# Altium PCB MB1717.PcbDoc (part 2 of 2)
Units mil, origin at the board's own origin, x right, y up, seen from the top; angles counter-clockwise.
Board outline 2760.94 x 3253.06 mil, 2 copper layers (Top Layer, Bottom Layer), stack 60.756 mil thick; 141 components, 128 nets, 519 pads, 417 vias.
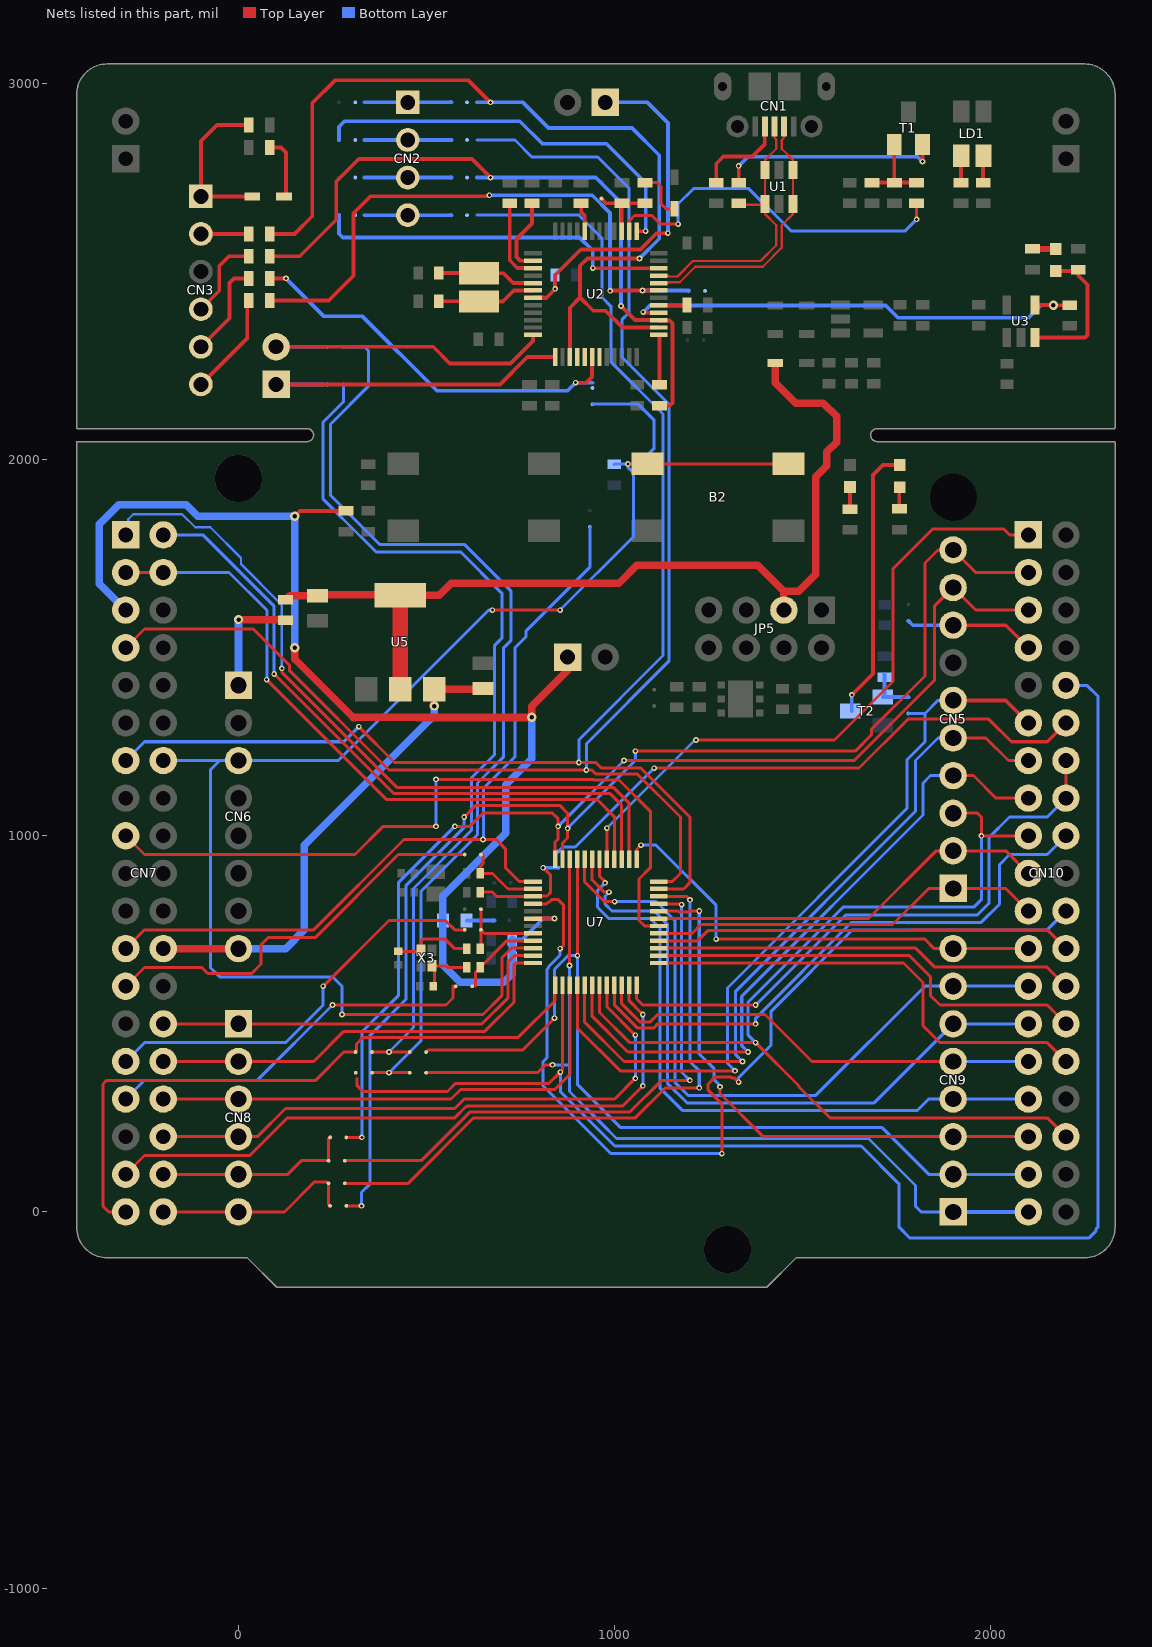
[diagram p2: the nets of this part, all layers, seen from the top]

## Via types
v1: diameter 15, hole 8, Top Layer to Bottom Layer, tented both sides, 383 vias
v2: diameter 25, hole 12, Top Layer to Bottom Layer, tented both sides, 19 vias
v3: diameter 15, hole 8, Top Layer to Bottom Layer, 15 vias

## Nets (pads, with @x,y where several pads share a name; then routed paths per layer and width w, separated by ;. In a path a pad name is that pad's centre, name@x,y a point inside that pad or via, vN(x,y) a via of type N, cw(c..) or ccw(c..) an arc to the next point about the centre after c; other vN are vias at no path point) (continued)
NetC25_2: C25.2 R33.1 X3.1 | length 220.4
  Top Layer w8: C25.2@425,692.72 482.28,692.72 X3.1@485.24,695.67 485.24,720.24 490,725 550,725 575,700 R33.1@607.28,700
NetC26_2: C26.2 R34.1 X3.3 | length 146.2
  Top Layer w8: X3.3@514.76,654.33 550.67,654.33 555,650 R34.1@607.28,650 ; C26.2@517.72,600 520.67,602.95 520.67,648.43 X3.3@522.24,650
NetCN1_4: CN1.4 R13.1 | length 244
  Top Layer w10: R13.1@1270,2740.5 1270,2787 1289,2806 1366,2806 1399.41,2839.41 CN1.4@1399.41,2885.79
NetCN2_1: CN2.1 SB11.2 SB12.1 | length 231.5
  Bottom Layer w10: 334.75,2950 CN2.1@450,2950 SB11.2@566.25,2950
NetCN2_2: CN2.2 SB13.2 SB14.1 | length 231.5
  Bottom Layer w10: 334.75,2850 CN2.2@450,2850 SB13.2@566.25,2850
NetCN2_3: CN2.3 SB15.2 SB16.1 | length 231.5
  Bottom Layer w10: 334.75,2750 CN2.3@450,2750 SB15.2@566.25,2750
NetCN2_4: CN2.4 SB17.2 SB18.1 | length 231.5
  Bottom Layer w10: 334.75,2650 CN2.4@450,2650 SB17.2@566.25,2650
NetCN3_1: CN3.1 D2.1 R1.1 | length 420.1
  Top Layer w10: R1.1@23.5,2890 -57,2890 -100,2847 CN3.1@-100,2700 D2.1@31.76,2700
NetCN3_2: CN3.2 R15.1 | length 123.5
  Top Layer w10: CN3.2@-100,2600 R15.1@23.5,2600
NetCN3_4: CN3.4 R18.1 | length 220.6
  Top Layer w10: CN3.4@-100,2400 -51,2449 -51,2515 -25,2541 R18.1@23.51,2541
NetCN3_5: CN3.5 R19.1 | length 254
  Top Layer w10: CN3.5@-100,2300 -24,2376 -24,2470 -12,2482 R19.1@23.51,2482
NetCN3_6: CN3.6 R20.1 | length 274.2
  Top Layer w10: CN3.6@-100,2200 23.51,2323.51 R20.1@23.51,2423
NetCN5_8: CN5.8 CN10.7 SB25.1 | length 348.6
  Top Layer w10: CN5.8@1900,1560 2040,1560 CN10.7@2100,1500
  Bottom Layer w10: SB25.1@1781,1571.38 1792.38,1560 CN5.8@1900,1560
NetCN6_1: CN6.1 R30.2 | length 301.1
  Top Layer w20: v2(0,1575) 122.44,1575 R30.2@125,1572.44
  Bottom Layer w20: CN6.1@0,1400 v2(0,1575)
NetCN7_25: CN7.25 SB3.2 | length 1089.5
  Top Layer w8: CN7.25@-300,600 -250,650 -97.63,650 -81.63,634 35,634 60,659 60,710 80,730 205,730 425,950 SB3.2@601.38,950
NetCN7_29: CN7.29 SB5.2 | length 1096.4
  Top Layer w8: v1(225,600) 400,775 550,775 575,750 SB5.2@601.38,750
  Bottom Layer w8: CN7.29@-300,400 -250,450 125,450 225,550 v1(225,600)
NetCN7_31: CN7.31 SB6.2 | length 1023.6
  Top Layer w8: v1(250,550) 551.38,550 570,568.62 570,592.24 ; 570,600 570,592.24 ; SB6.2@577.76,600 570,592.24
  Bottom Layer w8: CN7.31@-300,300 -250,350 50,350 v1(250,550)
NetCN7_36: CN7.36 CN8.5 SB7.1 SB8.2 | length 520.3
  Top Layer w8: CN7.36@-200,100 CN8.5@0,100 131,100 167,136 SB8.2@239.38,136 239.38,195.06 SB7.1@244.32,200
NetCN7_38: CN7.38 CN8.6 SB9.2 SB10.1 | length 529.4
  Top Layer w8: CN7.38@-200,0 CN8.6@0,0 122,0 201,79 235,79 ; SB9.2@239.38,76 239.38,19.94 SB10.1@243.32,16
NetCN10_12: CN10.12 SB4.1 | length 1541.2
  Top Layer w8: v3(1105,1180) 1650,1180 1780,1310 1995,1310 2055,1250 2150,1250 CN10.12@2200,1300
  Bottom Layer w8: SB4.1@850,958.31 861.69,970 895,970 v3(1105,1180)
NetD1_2: D1.2 R7.1 | length 133.7
  Top Layer w8: R7.1@1081,2736.56 1113.3,2736.56 1123.57,2726.29 1123.57,2680.46 1137.15,2666.87 D1.2@1159,2666.87
NetD2_2: D2.2 R2.1 | length 162
  Top Layer w10: R2.1@86.5,2830 113,2830 126.24,2816.76 D2.2@126.24,2700
NetL1_1: L1.1 SB30.2 | length 73.8
  Bottom Layer w10: L1.1@607.73,774.61 681.55,774.61
NetLD1_2: LD1.2 R12.2 | length 67.6
  Top Layer w10: LD1.2@1979.53,2807.94 1979.53,2740.97 R12.2@1980,2740.5
NetLD1_3: LD1.3 R11.2 | length 66.9
  Top Layer w10: R11.2@1921,2740.5 LD1.3@1921,2807.42
NetLD2_1: LD2.1 R16.1 | length 62
  Top Layer w16: R16.1@2111,2560.56 LD2.1@2172.97,2560.56
NetLD2_2: LD2.2 R17.1 U3.3 | length 386.2
  Top Layer w10: U3.3@2117.4,2324.69 2250.4,2324.69 2257,2331.29 2257,2465 2232.64,2489.36 R17.1@2232.64,2501.47 ; LD2.2@2173,2501.47 R17.1@2232.64,2501.47 ; R17.1@2232.64,2505.44 R17.1@2232.64,2501.47
NetLD3_1: LD3.1 R28.2 | length 58.6
  Top Layer w10: R28.2@1626,1868.56 LD3.1@1626,1927.17
NetLD4_1: LD4.1 R27.1 | length 58
  Top Layer w10: R27.1@1757,1868.86 1757,1925.47 LD4.1@1758,1926.47
NetLD4_2: LD4.2 T2.3 | length 733.5
  Top Layer w10: v1(1630.69,1374.69) 1687,1431 1687,1959.31 1713.21,1985.53 LD4.2@1758,1985.53
  Bottom Layer w10: T2.3@1630.69,1331 v1(1630.69,1374.69)
NetR3_2: R3.2 U2.3 | length 221.5
  Top Layer w10: R3.2@721,2681.44 721,2530 741.32,2509.68 U2.3@780,2509.68 ; U2.3@780,2508.9 U2.3@782.68,2508.9
NetR4_2: R4.2 U2.2 | length 207.4
  Top Layer w10: R4.2@780,2681.44 780,2628 739,2587 739,2539 749.42,2528.58 U2.2@782.68,2528.58
NetR5_2: R5.2 U2.44 | length 78
  Top Layer w10: R5.2@911,2681.44 911,2658.47 920.47,2649 U2.44@920.47,2607.32
NetR6_1: R6.1 R7.2 SB1.2 U2.39 | length 189.3
  Top Layer w10: SB1.2@965,2694.09 977.65,2681.44 R6.1@1020,2681.44 R7.2@1080,2681.44 ; U2.39@1018.9,2607.32 R6.1@1018.9,2676.4
NetR8_2: R8.2 T1.2 | length 595.8
  Top Layer w10: R8.2@1330,2740.5 v1(1330,2781) ; v1@1817,2791 v1(1818.4,2792.4) T1.2@1818.4,2837.69 ; T1.2@1820.58,2837.69 T1.2@1820.58,2841.63
  Bottom Layer w10: v1(1330,2781) 1354.58,2805.58 1805.22,2805.58 v1(1818.4,2792.4)
NetR9_2: R9.2 R10.1 R14.1 T1.1 | length 224.1
  Top Layer w10: R14.1@1684,2736.56 R10.1@1803,2736.56 ; R9.2@1743.42,2736.56 T1.1@1743.42,2841.63
NetR21_1: R21.1 U2.29 | length 75.3
  Top Layer w10: U2.29@1117.32,2410.47 1191.91,2410.47 R21.1@1192.44,2411
NetR35_1: R35.1 SB26.1 T2.1 | length 130.2
  Bottom Layer w10: T2.1@1713,1368.8 T2.1@1717.31,1368.8 ; T2.1@1717.31,1368.4 T2.1@1717.31,1368.8 ; R35.1@1718,1430.13 1717.31,1429.43 T2.1@1717.31,1368.8 ; SB26.1@1781,1368.31 1780.5,1368.8 T2.1@1717.31,1368.8
NetSB19_2: SB19.2
NetSB21_1: SB21.1 SB32.1 SB33.1 | length 2596.4
  Top Layer w8: SB32.1@355,370 v3(400,370) SB33.1@455.32,370
  Bottom Layer w8: SB21.1@279.68,2300 335,2300 345,2290 345,2195 245,2095 245,1905 375,1775 600,1775 725,1650 725,1520 705,1500 705,1210 635.5,1140.5 635.5,1003.08 485,852.58 485,455 v3(400,370)
NetSB22_1: SB22.1 SB27.1 SB31.1 | length 2351.1
  Top Layer w8: SB27.1@354.68,425 v3(400,425) SB31.1@455.32,425
  Bottom Layer w8: SB22.1@279.68,2200 279.68,2154.68 225,2100 225,1895 328.5,1791.5 329.08,1791.5 365.58,1755 590,1755 700,1645 700,1525 680,1505 680,1215 619.5,1154.5 619.5,1014.5 465,860 465,490 v3(400,425)
OSC_IN: C4.2 U2.5 X1.2 | length 268.1
  Top Layer w10: C4.2@524.69,2496 C4.2@532.56,2496 X1.2@639.4,2496 ; X1.2@640,2495.4 704.6,2495.4 730.47,2469.53 U2.5@782.68,2469.53
OSC_OUT: C5.2 U2.6 X1.1 | length 269.7
  Top Layer w10: C5.2@524.69,2421 C5.2@532.56,2421 X1.1@639.6,2421 ; X1.1@640,2420.6 702.6,2420.6 731.84,2449.84 U2.6@782.68,2449.84
PA0: CN7.28 CN8.1 U7.11 | length 1113.6
  Top Layer w8: CN7.28@-200,500 CN8.1@0,500 647.63,500 716,568.37 716,663.63 733.79,681.42 U7.11@782.68,681.42
PA1: CN7.30 CN8.2 U7.12 | length 1149.7
  Top Layer w8: CN7.30@-200,400 CN8.2@0,400 200,400 280,480 655,480 732,557 732,657 736.73,661.73 U7.12@782.68,661.73
PA2: CN7.37 SB27.2 U7.13 | length 1733.6
  Top Layer w8: CN7.37@-300,0 -345,0 -360,15 -360,340 -350,350 205,350 280,425 SB27.2@311.38,425 ; SB27.2@311.38,429.68 313.62,429.68 313.62,446.42 331.2,464 744,464 841.73,561.73 U7.13@841.73,602.68
PA3: CN10.10 SB32.2 U7.14 | length 4053.5
  Top Layer w8: 315.5,354.16 315.5,335.16 330.5,320.16 555.5,320.16 576.5,341.16 825.08,341.16 v1(855.5,371.57) 861.92,377.99 U7.14@861.92,602.83
  Bottom Layer w8: v1(855.5,371.57) 855.5,320.16 1000.5,175.16 1655.5,175.16 1755.5,75.16 1755.5,-39.84 1785.5,-69.84 2260.5,-69.84 2280.5,-49.84 2280.5,-44.84 2285.5,-39.84 2285.5,1370.16 2255.5,1400.16 CN10.10@2200.5,1400.16
PA4: CN7.32 CN8.3 U7.15 | length 1345.1
  Top Layer w8: CN7.32@-200,300 CN8.3@0,300 565,300 590,325 840,325 881.1,366.1 U7.15@881.1,602.68
PA5: CN5.6 CN10.11 SB26.2 U7.16 | length 2114.2
  Top Layer w8: U7.16@900.79,602.68 900.79,489.21 1015,375 v1(1320,375)
  Top Layer w10: CN5.6@1900,1360 CN5.6@1900,1360 2040,1360 CN10.11@2100,1300
  Bottom Layer w8: v1(1320,375) 1300,395 1300,595.37 1777.5,1072.87 1777.5,1202.5 1825,1250 1825,1325 ; SB26.2@1781,1325 1825,1325 ; CN5.6@1900,1360 1860,1360 1825,1325
PA6: CN5.5 CN10.13 U7.17 | length 1916.1
  Top Layer w8: U7.17@920.47,602.68 920.47,504.53 1025,400 v1(1340,400) ; CN5.5@1900,1260 1987,1260 2047,1200 CN10.13@2100,1200
  Bottom Layer w8: v1(1340,400) 1322,418 1322,587 1800,1065 1800,1200 1860,1260 CN5.5@1900,1260
PA7: CN5.4 CN10.15 U7.18 | length 1771.8
  Top Layer w8: U7.18@940.16,602.68 940.16,519.84 1035,425 v1(1355,425) ; CN5.4@1900,1160 1954,1160 2014,1100 CN10.15@2100,1100
  Bottom Layer w8: v1(1355,425) 1338,442 1338,573 1820,1055 1820,1140 1840,1160 CN5.4@1900,1160
PA8: CN10.24 U7.28 | length 1115.5
  Top Layer w8: U7.28@1117.32,720.79 1220.79,720.79 1247.84,747.84 1787.06,747.84 1789.21,750 2150,750 CN10.24@2200,700
PA9: CN5.1 CN10.21 U7.29 | length 1057
  Top Layer w8: U7.29@1117.32,740.47 1205.47,740.47 1228.84,763.84 1738.84,763.84 1835,860 CN5.1@1900,860 2040,860 CN10.21@2100,800
PA10: CN9.3 CN10.33 U7.32 | length 1485
  Top Layer w8: U7.32@1117.32,799.53 1167.9,799.53 1170.01,797.41 1196.21,797.41 1198.8,800 v3(1225,800) ; v3(1280.03,332.27) 1280.03,314.97 1395,200 CN9.3@1900,200 CN10.33@2100,200
  Bottom Layer w8: v3(1225,800) 1225,420 1264.6,380.4 1264.6,351.05 1276.53,339.12 1276.53,337.67 1280.03,334.17 v3(1280.03,332.27)
PA11: SB8.1 U7.33 | length 1543.7
  Top Layer w8: SB8.1@282.68,136 486,136 616,266 1041,266 1125,350 v1(1200,350) ; U7.33@1117.32,819.21 1175.79,819.21 v1(1178.09,816.91)
  Bottom Layer w8: v1(1178.09,816.91) 1178.09,371.91 v1(1200,350)
PA12: SB9.1 U7.34 | length 1644.2
  Top Layer w8: SB9.1@282.68,76 451,76 625,250 1055,250 1135,330 v1(1225,330) ; U7.34@1117.32,838.9 1191.1,838.9 v1(1200.55,829.45)
  Bottom Layer w8: v1(1200.55,829.45) 1200.55,399.45 1225,375 v1(1225,330)
PA13: CN7.13 SB17.1 U7.35 | length 3812.9
  Top Layer w8: v1(320,1290) 415,1195 v1(905,1195) 950,1195 964.5,1180.5 1069.5,1180.5 1200,1050 1200,875 1183.58,858.58 U7.35@1117.32,858.58
  Bottom Layer w8: CN7.13@-300,1200 -250,1250 280,1250 v1(320,1290) ; 633.75,2650 905,2650 967,2588 967,2430.91 990,2407.91 990,2260 1128.86,2121.14 1128.86,1479.32 905,1255.46 v1(905,1195)
PA14: CN7.7 SB13.1 U7.36 | length 4083.3
  Top Layer w8: CN7.7@-300,1500 -250,1550 -26.81,1550 -26.66,1549.84 39.05,1549.84 135,1453.89 135,1440 400,1175 v1(925,1175) 939.5,1175 950,1164.5 1060.5,1164.5 1175,1050 1175,900 1153.27,878.27 U7.36@1117.32,878.27
  Bottom Layer w8: 633.75,2850 735,2850 780,2805 955,2805 1038.28,2721.72 1038.28,2391 1019.08,2371.8 1019.08,2272.92 1144.86,2147.14 1144.86,2080.14 1145,2080 1145,1465 925,1245 v1(925,1175)
PA15: CN9.8 CN10.23 U7.37 | length 1239.2
  Top Layer w8: U7.37@1058.27,937.32 1058.27,963.27 v1(1070,975) ; v3(1270,725) 1825,725 1850,700 CN9.8@1900,700 CN10.23@2100,700
  Bottom Layer w8: v1(1070,975) 1110,975 1270,815 v3(1270,725)
PB0: CN5.3 CN10.17 CN10.34 U7.19 | length 2724.6
  Top Layer w8: U7.19@959.84,602.68 959.84,530.16 1040,450 v1(1375,450) 1490.5,334.5 1490.5,331.92 1572.42,250 2150,250 CN10.34@2200,200 ; CN5.3@1900,1060 1965,1060 1975,1050 v3(1975,1000) CN10.17@2100,1000
  Bottom Layer w8: v1(1375,450) 1354,471 1354,556.58 1607.42,810 1955,810 1975,830 v3(1975,1000)
PB1: CN7.34 CN8.4 U7.20 | length 1598.1
  Top Layer w8: CN7.34@-200,200 -16,200 CN8.4@-16,184 ; CN8.4@0,200 50,200 125,275 575,275 600,300 1000,300 v1(1055,355) ; U7.20@979.53,602.68 979.53,545.47 v1(1055,470)
  Bottom Layer w8: v1(1055,355) v1(1055,470)
PB2: CN10.18 U7.21 | length 1560
  Top Layer w8: U7.21@999.21,602.68 999.21,550.53 1049.75,500 1049.8,500 1060.3,489.5 1104.5,489.5 1115,500 v1(1375,500)
  Bottom Layer w8: v1(1375,500) 1375,515 1630,770 1975,770 2023,818 2023,923 2050,950 2150,950 CN10.18@2200,1000
PB3: CN9.4 CN10.31 U7.42 | length 1772.2
  Top Layer w8: U7.42@959.84,937.32 959.84,892.73 975,877.58 v1(975,875)
  Bottom Layer w8: v1(975,875) 955,855 955,810.25 957.17,808.09 957.17,807.33 984.75,779.75 1095.25,779.75 1120,755 1120,330 1180,270 1805,270 1835,300 CN9.4@1900,300 CN10.31@2100,300
PB4: CN9.6 CN10.27 U7.43 | length 1827.8
  Top Layer w8: U7.43@940.16,937.32 940.16,882.27 972.42,850 v1(985,850)
  Bottom Layer w8: v1(985,850) 975,840 975,818 993,800 1105,800 1140,765 1140,342.17 1192.17,290 1690,290 CN9.6@1900,500 CN10.27@2100,500
PB5: CN9.7 CN10.25 U7.44 | length 1873.9
  Top Layer w8: U7.44@920.47,937.32 920.47,876.95 972.42,825 v1(1000,825) ; CN10.25@2073,600 CN10.25@2100,600
  Bottom Layer w8: v1(1000,825) 1110,825 1160,775 1160,344.8 1194.8,310 1535,310 1825,600 CN9.7@1900,600 CN10.25@2100,600
PB6: CN9.2 CN10.35 SB31.2 U7.45 | length 2480.8
  Top Layer w8: SB31.2@498.62,425 503.62,430 755,430 v3(840,515) ; v1(900.79,681.11) U7.45@900.79,937.32
  Bottom Layer w8: v3(840,515) 840,645 876.11,681.11 v1(900.79,681.11) 900.79,339.21 1015,225 1710,225 1835,100 CN9.2@1900,100 CN10.35@2100,100
PB7: CN9.1 CN10.37 SB33.2 U7.46 | length 2393.1
  Top Layer w8: SB33.2@498.62,370 795,370 816.07,391.07 v3(834.82,391.07) ; v1(880,655) 880.5,655.5 880.5,936.72 U7.46@881.1,937.32
  Bottom Layer w8: v3(834.82,391.07) 878.93,391.07 880,390 ; v1(880,655) 880,390 ; CN9.1@1900,0 1815,0 1800,15 1800,70 1675,195 1005.2,195 964.7,235.5 964.5,235.5 880,320 880,390
  Bottom Layer w10: CN9.1@1900,0 CN10.37@2100,0
PB8: CN5.10 CN10.3 SB10.2 U7.47 | length 3367.6
  Top Layer w8: SB10.2@286.62,16 v1(327,16) ; v1(600,1050) 631,1081 854,1081 875,1060 v1(875,1020) 875,993.91 861.42,980.33 U7.47@861.42,937.32 ; v1(1055,1225) 1639.58,1225 1682.5,1267.92 1682.5,1282.5 1825,1425 1825,1725 1860,1760 CN5.10@1900,1760 1960,1700 CN10.3@2100,1700
  Bottom Layer w8: v1(327,16) 327,52 350,75 350,470 445,565 445,867.42 600,1022.42 v1(600,1050) ; v1(875,1020) 1055,1200 v1(1055,1225)
PB9: CN5.9 CN10.5 SB7.2 U7.48 | length 3024.5
  Top Layer w8: 293,198 v1(328,198) ; v1(575,1025) 615,1025 650,1060 835,1060 850,1045 v1(850,1025) 850,991.54 841.73,983.27 U7.48@841.73,937.32 ; v1(1025,1200) 1637.2,1200 1850,1412.8 1850,1610 CN5.9@1900,1660 1960,1600 CN10.5@2100,1600
  Bottom Layer w8: v1(328,198) 328,478 425,575 425,875 v1(575,1025) ; v1(850,1025) v1(1025,1200)
PB10: CN9.5 CN10.29 U7.22 | length 1210
  Top Layer w8: U7.22@1018.9,602.68 1018.9,553.47 1056.37,516 1056.42,516 1066.92,505.5 1095,505.5 1114.5,525 1400,525 1525,400 CN9.5@1900,400
  Bottom Layer w8: CN9.5@1900,400 CN10.29@2100,400
PB11: CN7.35 U7.23 | length 1755.1
  Top Layer w8: CN7.35@-300,100 -250,150 30,150 130,250 575,250 605,280 607.37,280 609.37,282 1022,282 v1(1075,335) ; U7.23@1038.58,602.68 1038.58,561.42 v1(1075,525)
  Bottom Layer w8: v1(1075,335) v1(1075,525)
PB12: CN10.14 CN10.16 U7.24 | length 1614.9
  Top Layer w8: U7.24@1058.27,602.68 1058.27,566.73 1075,550 v1(1375,550) ; CN10.16@2200,1100 CN10.14@2200,1200
  Bottom Layer w8: v1(1375,550) 1615,790 1965,790 1995,820 1995,995 2050,1050 2150,1050 CN10.16@2200,1100
PB13: CN10.30 U7.25 | length 1258.5
  Top Layer w8: U7.25@1117.32,661.73 1768.27,661.73 1820,610 1820,495 1865,450 2150,450 CN10.30@2200,400
PB14: CN10.28 U7.26 | length 1187.1
  Top Layer w8: U7.26@1117.32,681.42 1783.58,681.42 1840,625 1840,575 1865,550 2150,550 CN10.28@2200,500
PB15: CN10.26 U7.27 | length 1124.6
  Top Layer w8: U7.27@1117.32,701.1 1800.48,701.1 1850,651.58 2148.42,651.58 CN10.26@2200,600
PC6: CN7.17 U7.30 | length 1967.9
  Top Layer w8: CN7.17@-300,1000 -250,950 310,950 385,1025 v3(525,1025) ; v3(525,1150) 941.87,1150 943.37,1148.5 1011.5,1148.5 1095,1065 1095,915 1065,885 1065,775 1079.84,760.16 U7.30@1117.32,760.16
  Bottom Layer w8: v3(525,1025) v3(525,1150)
PC7: CN5.2 CN10.19 U7.31 | length 1082.2
  Top Layer w8: U7.31@1117.32,779.84 1674.84,779.84 1855,960 CN5.2@1900,960 2040,960 CN10.19@2100,900
PC13: CN7.23 SB24.1 U7.1 | length 2227.4
  Top Layer w8: CN7.23@-300,700 -250,750 200,750 440,990 v1(650,990) 685,990 709.5,965.5 709.5,915.5 746.73,878.27 U7.1@782.68,878.27
  Bottom Layer w8: v1(650,990) 651.5,991.5 651.5,1126.5 735,1210 735,1500 765,1530 765,1545 934.11,1714.11 SB24.1@934.11,1821.31
PC14: R31.2 SB3.1 U7.2 | length 210.1
  Top Layer w8: 650,950 650,925 642.72,917.72 R31.2@642.72,900 675,900 716.42,858.58 U7.2@782.68,858.58
PC15: R32.2 SB4.2 U7.3 | length 309.8
  Top Layer w8: R32.2@642.72,850 675,850 686.1,838.9 U7.3@782.68,838.9 783.78,840 820,840 830,850 830,895 v3(810,915)
  Bottom Layer w8: v3(810,915) SB4.2@850,915
PD0: CN7.1 U7.38 | length 1963.5
  Top Layer w8: v1(115,1445) 115,1435 421,1129 996,1129 1038.58,1086.42 U7.38@1038.58,937.32
  Bottom Layer w6: CN7.1@-300,1800 -293.1,1806.9 -293.1,1841.9 -280,1855 -150,1855 -115,1820 -75,1820 6.5,1738.5 6.5,1722.34 115,1613.84 v1(115,1445)
PD1: CN7.2 U7.39 | length 1765.9
  Top Layer w8: v1(95,1430) 412,1113 987,1113 1018.9,1081.1 U7.39@1018.9,937.32
  Bottom Layer w8: CN7.2@-200,1800 -95,1800 95,1610 v1(95,1430)
PD2: CN7.3 CN7.4 U7.40 | length 1790.4
  Top Layer w8: CN7.3@-300,1700 CN7.4@-200,1700 ; v1(75,1415) 393,1097 953,1097 999.21,1050.79 U7.40@999.21,937.32
  Bottom Layer w8: CN7.4@-200,1700 -25,1700 75.5,1599.5 75.5,1415.5 v1(75,1415)
PD3: CN10.1 U7.41 | length 1714.7
  Top Layer w8: U7.41@979.53,937.32 v1(979.53,1020.47) ; v1(1216.48,1254.68) 1584.68,1254.68 1740,1410 1740,1710 1845,1815 2035,1815 2050,1800 CN10.1@2100,1800
  Bottom Layer w8: v1(979.53,1020.47) 1213.74,1254.68 v1(1216.48,1254.68)
PF0: R33.2 SB5.1 SB29.1 U7.8 | length 247.8
  Top Layer w8: R33.2@642.72,700 644.68,701.97 SB5.1@644.68,750 ; SB29.1@644.68,805 SB5.1@644.68,750 ; U7.8@782.68,740.47 654.21,740.47 SB5.1@644.68,750
PF1: R34.2 SB6.1 U7.9 | length 224.5
  Top Layer w8: 630,600 630,637.28 R34.2@642.72,650 713.5,720.79 U7.9@782.68,720.79
PF2: B2.3 B2.4 C28.2 CN6.3 CN7.14 SB23.2 U7.10 | length 4148.7
  Top Layer w8: v1(275,525) 650,525 700,575 700,675 726.1,701.1 U7.10@782.68,701.1 ; v1(675,1600) v1(855,1600) ; v1(1035,1988.58) B2.4@1087.99,1988.58 B2.3@1462.01,1988.58
  Bottom Layer w8: CN7.14@-200,1200 -50,1200 ; v1(275,525) 275,600 250,625 -50,625 -75,650 -75,1175 -50,1200 ; v1(675,1600) 665.35,1600 265.35,1200 CN6.3@0,1200 -50,1200 ; v1(855,1600) 1050,1795 1050,1965 1035,1980 v1(1035,1988.58) ; SB23.2@941,2147.38 1062.62,2147.38 1105,2105 1105,2030 1063.58,1988.58 v1(1035,1988.58) ; C28.2@999,1987.53 1000.05,1988.58 v1(1035,1988.58)
PF3: CN10.22 U7.4 | length 2558.5
  Top Layer w8: U7.4@782.68,819.21 819.14,819.21 823.92,824 826.63,824 832.63,830 850,830 864.5,815.5 864.5,709.5 v3(855,700) ; v3(1285,155) 1285,287.37 1248.6,323.77 1248.6,339.9 1267.7,359 1308.42,359 1311.92,355.5 1319.5,355.5 v3(1330,345)
  Bottom Layer w8: v3(855,700) 855,682.63 824,651.63 824,649 820,645 820,410 810,400 810,335 990,155 v3(1285,155) ; v3(1330,345) 1330,357.42 1416.31,443.74 1416.31,533.69 1632.63,750 2150,750 CN10.22@2200,800
PWR_ENn: R22.1 U2.28 U3.4 | length 1260.5
  Top Layer w10: v1(1076,2392) 1077.21,2390.79 U2.28@1117.32,2390.79 ; U3.4@2117.4,2411.31 2166,2411.31 v2(2166.75,2410.56) R22.1@2210,2410.56
  Bottom Layer w10: v1(1076,2392) 1094,2410 1721,2410 1754,2377 2099.83,2377 2133.39,2410.56 v2(2166.75,2410.56)
STL_USB_D_N: CN1.2 U1.1 U1.6 U2.32 | length 714.6
  Top Layer w6.1: U2.32@1117.32,2469.53 1141,2469.53 1143.35,2471.87 1173.04,2471.87 1214.17,2513 1393.71,2513 1444.5,2563.79 1444.5,2623.1 1474.4,2653 U1.6@1474.4,2679.72 U1.1@1474.4,2770.28 1474.4,2797 1444.5,2826.9 1444.5,2849 ; 1444.5,2849.91 1450.59,2856 CN1.2@1450.59,2885.79
STL_USB_D_P: CN1.3 R8.1 U1.3 U1.4 U2.33 | length 757.2
  Top Layer w6.1: U2.33@1117.32,2489.21 1141,2489.21 1143.35,2486.87 1166.82,2486.87 1207.95,2528 1387.5,2528 1429.5,2570 1429.5,2623.1 1399.6,2653 U1.4@1399.6,2677.76 ; R8.1@1330,2677.5 1399.35,2677.5 U1.4@1399.6,2677.76 ; CN1.3@1425,2885.79 1425,2856 1429.5,2851.5 ; 1429.5,2849 1429.5,2826.9 1399.6,2797 U1.4@1399.6,2677.76
STLK_RX: JP4.1 SB22.2 U2.13 | length 898.1
  Top Layer w10: JP4.1@100,2200 695,2200 767.68,2272.68 U2.13@841.73,2272.68
  Bottom Layer w10: JP4.1@100,2200 226.25,2200
STLK_TX: JP4.2 SB21.2 U2.12 | length 867.9
  Top Layer w10: JP4.2@100,2300 517.89,2300 561.89,2256 723,2256 782.68,2315.68 U2.12@782.68,2331.73
  Bottom Layer w10: JP4.2@100,2300 226.25,2300
STM_JTCK: SB14.2 U2.37 | length 1077.4
  Top Layer w10: U2.37@1058.27,2607.32 v1(1082.68,2607.32)
  Bottom Layer w10: SB14.2@267.25,2850 267.25,2885.25 282,2900 748,2900 808,2840 978,2840 1082.68,2735.32 v1(1082.68,2607.32)
STM_JTMS: SB18.2 U2.34 | length 964.9
  Top Layer w10: v1(942,2509) 942.1,2508.9 U2.34@1117.32,2508.9
  Bottom Layer w10: SB18.2@267.25,2650 267.25,2600.75 277,2591 907,2591 942,2556 v1(942,2509)
STM_RST: C27.1 JP1.1 U2.7 | length 1031.5
  Top Layer w10: 811.68,2430.94 783.46,2430.94 U2.7@782.68,2430.16 ; 813.23,2430.16 U2.7@782.68,2430.16 ; v1(1141.64,2602) 1111.57,2602 1068.57,2559 910.08,2559 842,2490.92 v1(842,2454) 818.16,2430.16 U2.7@782.68,2430.16
  Bottom Layer w10: C27.1@841.44,2491 841.44,2454.56 v1(842,2454) ; JP1.1@975,2950 1087,2950 1141.64,2895.36 v1(1141.64,2602)
T_JRST: U2.19
T_JTCK: R15.2 SB11.1 U2.15 U2.26 | length 2454.6
  Top Layer w10: R15.2@86.5,2600 149,2600 196,2647 196,2947.99 256.46,3008.44 611.56,3008.44 v1(670,2950) ; U2.15@881.1,2272.68 881.1,2404.1 908,2431 ; v1(1066,2535) 927.67,2535 908,2515.33 908,2431 ; U2.26@1117.32,2351.42 1020.58,2351.42 976,2396 943,2396 908,2431
  Bottom Layer w10: 633.75,2950 v1(670,2950) 756,2950 824,2882 1046,2882 1118.5,2809.5 1118.5,2587.5 v1(1066,2535)
T_JTDI: U2.17
T_JTDO: U2.16
T_JTMS: R18.2 R25.2 SB15.1 U2.27 | length 1863.2
  Top Layer w10: R18.2@86.5,2541 163,2541 260,2638 260,2739.5 319.92,2799.42 620.58,2799.42 v1(670,2750) ; v1@1017,2407 v1(1017,2408.4) 1054.3,2371.1 U2.27@1117.32,2371.1 1118.1,2370.32 1146.33,2370.32 1153.94,2362.71 1153.94,2150.94 1146.44,2143.44 R25.2@1119,2143.44
  Bottom Layer w10: 633.75,2750 v1(670,2750) 950,2750 1017,2683 v1(1017,2408.4)
T_NRST: R19.2 SB23.1 U2.18 | length 1089.9
  Top Layer w10: R19.2@86.5,2482 v1(126.24,2482) ; v1(896.5,2204.75) 924.75,2204.75 940.16,2220.16 U2.18@940.16,2272.68
  Bottom Layer w10: v1(126.24,2482) 227.25,2381 330,2381 528,2183 874.75,2183 v1(896.5,2204.75) 941,2204.75
T_SWDIO_IN: R25.1 U2.25 | length 129.9
  Top Layer w10: U2.25@1117.32,2331.73 1119,2330.06 R25.1@1119,2202.5
T_SWO: R20.2 SB19.1 U2.31 | length 1594.1
  Top Layer w10: R20.2@86.5,2423 239.75,2423 305.75,2489 305.75,2655.35 350.98,2700.58 664.55,2700.58 v1(666.97,2703) ; v1(988,2449) 988.84,2449.84 v1(1074,2449.84) U2.31@1117.32,2449.84
  Bottom Layer w10: v1(666.97,2703) 940.75,2703 988,2655.75 v1(988,2449) ; v1(1074,2449.84) SB19.1@1197.16,2449.84
USB_RENUMn: R10.2 U2.38 | length 976.5
  Top Layer w8: U2.38@1038.58,2607.32 1038.58,2634.58 1053,2649 1099,2649 1121.9,2626.1 v1(1168.78,2626.1) ; R10.2@1803,2677.5 1803,2639.25 v1(1803.25,2639)
  Bottom Layer w8: v1(1168.78,2626.1) 1168.78,2679.78 1209.47,2720.47 1356.88,2720.47 1470.03,2607.32 1771.57,2607.32 v1(1803.25,2639)
VDD: C32.2 C33.2 CN7.5 JP6.1 L1.2 R29.2 U7.6 | length 3482.8
  Top Layer w10: v2(149.5,1849.5) 163.56,1863.56 R29.2@286,1863.56 ; U7.6@782.68,779.84 v1@840,779.84
  Top Layer w20: v2(150,1500) 150,1470 305.5,1314.5 308.44,1314.5 309.44,1315.5 474,1315.5 475,1314.5 779.5,1314.5 v2(780,1315) 780,1345 875,1440 JP6.1@875,1475
  Bottom Layer w10: C32.2@727.56,725 755,725 810,780 v1(840,780)
  Bottom Layer w20: CN7.5@-300,1600 -370,1670 -370,1828.29 -318.29,1880 -139,1880 -108.5,1849.5 v2(149.5,1849.5) 150,1850 v2(150,1500) ; C32.2@727.56,725 C33.2@727.56,675 727.56,632.56 705,610 590,610 543.5,656.5 L1.2@543.5,775 543.5,839.62 710,1006.11 710,1135.91 779.09,1205 779.09,1314.09 v2(780,1315)
VIN: C18.2 CN6.8 CN7.24 U5.3 | length 1305.8
  Top Layer w20: CN7.24@-200,700 CN6.8@0,700 ; v2(520.55,1345) U5.3@520.55,1390 ; U5.3@523,1390 C18.2@650,1390
  Bottom Layer w20: CN6.8@0,700 125,700 175,750 175,975 520.55,1320.55 v2(520.55,1345)
VIN_5V: C17.2 D5.1 JP5.3 R30.1 U5.2 U5.4 | length 2490.1
  Top Layer w20: R30.1@125,1627.56 135.91,1638.46 C17.2@210,1638.46 ; C17.2@210,1641 U5.4@430,1641 ; U5.4@430,1640 534,1640 566,1672 1011.6,1672 1059.1,1719.5 1380.5,1719.5 1450,1650 ; D5.1@1426.87,2257 1426.87,2205 1481.87,2150 1555,2150 1590,2115 1590,2046.78 1564.25,2021.03 1564.25,1984.25 1535,1955 1535,1695 1490,1650 1450,1650 ; JP5.3@1450,1600 1450,1650
  Top Layer w40: U5.2@430,1390 U5.4@430,1640
pads on no net: CN7.9 CN7.10 CN7.11 CN7.15 CN7.21 CN7.26 CN7.27 CN7.33 CN10.2 CN10.4 CN10.6 CN10.36 CN10.38 U2.4 U2.11 U2.14 U2.21 U2.22 U2.40 U2.41 U2.42 U2.43 U2.45 U2.46 U6.3 U6.5

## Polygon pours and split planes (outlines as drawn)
GND on Top Layer "GND" (solid, remove dead copper, pour order 21): -429.42,-38.49 ccw(c-348.16,-38.49) -348.16,-119.75 ccw(c-348.16,-117.23) -348.13,-119.75 24.81,-119.75 102.81,-197.75 ccw(c104.59,-195.97) 104.59,-198.49 1403.8,-198.49 ccw(c1403.8,-195.97) 1405.58,-197.75 1405.59,-197.74 cw(c1403.81,-195.97) 1405.57,-197.76 1483.59,-119.75 2250.26,-119.75 ccw(c2250.26,-38.49) 2331.52,-38.49 2331.52,2048.12 ccw(c2329,2048.12) 2329,2050.64 1699.08,2050.64 cw(c1699.08,2067.81) 1699.08,2084.98 2328.98,2084.98 ccw(c2329,2087.49) 2331.52,2087.49 2331.52,2973.32 ccw(c2250.26,2973.32) 2250.28,3054.58 ccw(c2250.27,2973.26) 2250.26,3054.58 cw(c2250.26,3052.06) 2250.28,3054.58 2250.26,3054.58 -348.16,3054.58 ccw(c-348.16,3052.06) -348.19,3054.58 cw(c-348.18,2973.26) -348.16,3054.58 -348.19,3054.58 ccw(c-348.16,2973.32) -429.42,2973.32 -429.42,2087.49 ccw(c-426.9,2087.49) -426.87,2084.98 183.33,2084.98 cw(c183.33,2067.81) 200.5,2067.81 cw(c183.33,2067.81) 183.33,2050.64 -426.9,2050.64 ccw(c-426.9,2048.12) -429.42,2048.1
VIN_5V on Top Layer "VIN_5V" (solid, remove dead copper, pour order 18): 190,1680 176,1680 ccw(c176,1659) 155,1659 155,1616.37 ccw(c161.37,1616.37) 161.37,1610 290,1610 cw(c290,1600) 300,1600 300,1471 ccw(c321,1471) 321,1450 380,1450 cw(c380,1430) 400,1430 400,1358.63 ccw(c410,1358.63) 410,1348.63 453.37,1348.63 ccw(c453.37,1355.25) 460,1355.25 460,1432.56 cw(c477.44,1432.56) 477.44,1450 554.76,1450 ccw(c554.76,1465) 569.76,1465 569.76,1665.24 ccw(c555,1665.24) 555,1680
GND on Bottom Layer "GND" (solid, remove dead copper, pour order 22): -429.42,-38.49 ccw(c-348.16,-38.49) -348.16,-119.75 ccw(c-348.16,-117.23) -348.13,-119.75 24.81,-119.75 102.81,-197.75 ccw(c104.59,-195.97) 104.59,-198.49 1403.8,-198.49 ccw(c1403.8,-195.97) 1405.58,-197.75 1405.59,-197.74 cw(c1403.81,-195.97) 1405.57,-197.76 1483.59,-119.75 2250.26,-119.75 ccw(c2250.26,-38.49) 2331.52,-38.49 2331.52,2048.12 ccw(c2329,2048.12) 2329,2050.64 1699.08,2050.64 cw(c1699.08,2067.81) 1699.08,2084.98 2328.98,2084.98 ccw(c2329,2087.49) 2331.52,2087.49 2331.52,2973.32 ccw(c2250.26,2973.32) 2250.28,3054.58 ccw(c2250.27,2973.26) 2250.26,3054.58 cw(c2250.26,3052.06) 2250.28,3054.58 2250.26,3054.58 -348.16,3054.58 ccw(c-348.16,3052.06) -348.19,3054.58 cw(c-348.18,2973.26) -348.16,3054.58 -348.19,3054.58 ccw(c-348.16,2973.32) -429.42,2973.32 -429.42,2087.49 ccw(c-426.9,2087.49) -426.87,2084.98 183.33,2084.98 cw(c183.33,2067.81) 200.5,2067.81 cw(c183.33,2067.81) 183.33,2050.64 -426.9,2050.64 ccw(c-426.9,2048.12) -429.42,2048.1

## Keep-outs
Keep-Out Layer:
  lines w5: 1480.32,-119.75 2249.22,-119.75 ccw(c2249.22,-41.01) 2327.96,-41.01 2327.96,2045.61 1698.04,2045.61 cw(c1698.04,2065.29) 1698.04,2084.98 2327.96,2084.98 2327.96,2970.81 ccw(c2249.22,2970.81) 2249.22,3049.55 -349.21,3049.55 ccw(c-349.21,2970.8) -427.95,2970.8 -427.95,2084.98 182.29,2084.98 cw(c182.29,2065.29) 182.29,2045.61 -427.95,2045.61 -427.95,-41.01 ccw(c-349.21,-41.01) -349.21,-119.75 19.69,-119.75 24.81,-119.75 103.55,-198.49 1402.76,-198.49 ; 1481.5,-119.75 1402.76,-198.49 ; 1402.76,-198.49 1402.76,-198.49 ; 320.09,2045.61 cw(c320.09,2065.29) 320.09,2084.98 1068.12,2084.98 cw(c1068.12,2065.29) 1068.12,2045.61 320.09,2045.61 ; 1250.01,2045.61 cw(c1250.01,2065.29) 1250.01,2084.98 1538.59,2084.98 cw(c1538.59,2065.29) 1538.59,2045.61 1250.01,2045.61

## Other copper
Top Layer:
  text ".Layer_Name" at -580.66,-754.37 h118.11
  text ".GTL" at 1060.87,-754.37 h118.11
Bottom Layer:
  text ".GBL" at 619.79,-755.63 h118.11
  text ".Layer_Name" at 2246.33,-755.63 h118.11

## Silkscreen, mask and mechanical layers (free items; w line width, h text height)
Top Overlay:
  region: 561,2767.57 531,2767.57 531,2632.06 561,2632.06
  region: 561,2967.57 531,2967.57 531,2832.06 561,2832.06
  lines w4.72: 816.22,2312.05 822.05,2306.22 839.76,2306.22 ; 816.22,2567.95 822.05,2573.78 ; 1068.11,2573.78 1076.22,2573.78 1085.78,2564.22 1085.78,2556.14 ; 1077.95,2306.22 1085.78,2314.05 1085.78,2327.8 ; 822.05,2573.78 822.05,2573.78
  lines w5: 55.32,1140 181,1140 181,1010 ; 60,-50 181,-50 181,197 ; 60,550 181,550 181,323 ; 60,650 181,650 181,793
  lines w12: 339,2622.57 339,2757.06 369,2757.06 369,2622.57 339,2622.57 ; 339,2832.06 369,2832.06 369,2967.57 339,2967.57 339,2832.06
  text "USB_" at 1601,3000 h39.37
  text "STLINK" at 1743.42,3000 h39.37
  text "STLK_RST" at 1047.05,2900 h30
  text "GND" at 2130,2811 h39.37 r90
  text "GND" at -185,2807.36 h39.37 r90
  text "COM" at 2070,2790 h39.37 r90
  text "NUCLEO" at 624.65,2700 h40 r90
  text "ST-LINK" at 316,2685 h40 r90
  text "SWD" at -170,2420 h40 r90
  text "TX" at 169,2279.3 h40
  text "RX" at 170,2179.3 h40
  text "USER" at 923,1825 h40 r90
  text "RESET" at 1013,1824 h40 r90
  text "SCL/D15" at 1613.22,1723 h40
  text "CHG" at 1265,1665 h39.37 r90
  text "E5V" at 1365.04,1665 h39.37 r90
  text "VIN" at 1469.98,1665 h39.37 r90
  text "STLK" at 1573.54,1665 h39.37 r90
  text "SDA/D14" at 1627,1630 h35
  text "E5V" at -138,1571 h40
  text "AVDD" at 1699.17,1530 h40
  text "GND" at -140,1483 h40
  text "GND" at 1734.78,1436 h40
  text "IDD" at 897,1361 h39.37
  text "SCK/D13" at 1604.9,1334 h40
  text "IOREF" at 63,1280 h40
  text "MISO/D12" at 1590.24,1237.5 h40
  text "NRST" at 63,1170 h40
  text "PWM/MOSI/D11" at 1454.46,1130 h40
  text "3V3" at 63,1080 h40
  text "L" at 765,1075 h400
  text "PWM/CS/D10" at 1487.6,1030 h40
  text "K" at 245,1025 h400
  text "5V" at 63,973 h40
  text "PWM/D9" at 1623.57,930 h40
  text "GND" at 63,876 h40
  text "D8" at 1774.58,830 h40
  text "POWER" at 222,820 h40 r90
  text "GND" at 63,779 h40
  text "VIN" at 63,678.09 h40
  text "D7" at 1774.58,670 h40
  text "J" at 1240,585 h600
  text "PWM/D6" at 1623.57,570 h40
  text "LQFP48" at 748.57,510 h40
  text "A0" at 63,470 h40
  text "PWM/D5" at 1621.66,470 h40
  text "A1" at 63,370 h40
  text "D4" at 1772.68,370 h40
  text "A2" at 63,270 h40
  text "PWM/D3" at 1621.66,270 h40
  text "AIN" at 195,216 h40 r90
  text "A3" at 63,170 h40
  text "D2" at 1769.58,170 h40
  text "TX/D1" at 1690.36,79.72 h40
  text "A4" at 63,70 h40
  text "RX/D0" at 1669.03,-25.59 h40
  text "A5" at 63,-30 h40
  text "MB1717B" at 510,-120 h98.43
  text ".Layer_Name" at -580.66,-754.37 h118.11
  text ".GTO" at 1060.87,-754.37 h118.11
Bottom Overlay:
  drawing of 278 lines, arcs and shapes, not listed
  text "JP1" at 1143,2925 h40
  text "CN1" at 1442,2778 h35
  text "JP2" at -245,2695.95 h35
  text "JP3" at 2255,2695.95 h35
  text "RESERVED" at 341.2,2530 h40
  text "CN4" at 492,2530 h40
  text "DEFAULT" at 780,2530 h40
  text "SWD" at -220,2390 h40 r270
  text "MCO" at 1146.85,2302 h39.37
  text "TX" at 38.98,2275 h40
  text "RX" at 38.98,2182 h40
  text "CN3" at -190,2120 h35
  text "JP4" at 155,2095.95 h35
  text "CHG" at 1260,1670 h39.37 r90
  text "E5V" at 1334.45,1670 h39.37 r270
  text "VIN" at 1427.16,1670 h39.37 r270
  text "STLK" at 1535.93,1670 h39.37 r270
  text "JP6" at 983,1540 h35
  text "JP5" at 1179,1527 h35
  text "E" at 1440,1025 h400
  text "H" at 1455,805 h400
  text "CN5" at 1951,760 h35
  text "CN6" at 49,583 h35
  text "F" at 1445,485 h400
  text "G" at 1090,400 h400
  text "C" at 425,200 h400
  text "I" at 390,-90 h400
  text "CN7" at -190,-102 h35
  text "CN8" at 55,-102 h35
  text "CN9" at 1949,-102 h35
  text "CN10" at 2219,-102 h35
  text ".GBO" at 619.79,-755.63 h118.11
  text ".Layer_Name" at 2246.33,-755.63 h118.11
Top Paste:
  text ".Layer_Name" at -580.66,-754.37 h118.11
  text ".GTP" at 1060.87,-754.37 h118.11
Bottom Paste:
  text ".GBP" at 619.79,-755.63 h118.11
  text ".Layer_Name" at 2246.33,-755.63 h118.11
Top Solder:
  text ".Layer_Name" at -580.66,-754.37 h118.11
  text ".GTS" at 1060.87,-754.37 h118.11
Bottom Solder:
  text ".GBS" at 619.79,-755.63 h118.11
  text ".Layer_Name" at 2246.33,-755.63 h118.11
M1-Board Shape:
  lines w5: 1480.32,-119.69 2249.22,-119.69 ccw(c2249.22,-40.95) 2327.96,-40.95 2327.96,2045.67 1698.04,2045.67 cw(c1698.04,2065.35) 1698.04,2085.04 2327.96,2085.04 2327.96,2970.87 ccw(c2249.22,2970.87) 2249.22,3049.61 -349.21,3049.61 ccw(c-349.21,2970.87) -427.95,2970.87 -427.95,2085.04 182.29,2085.04 cw(c182.29,2065.35) 182.29,2045.67 -427.95,2045.67 -427.95,-40.95 ccw(c-349.21,-40.95) -349.21,-119.69 19.69,-119.69 24.81,-119.69 103.55,-198.43 1402.76,-198.43 ; 1481.5,-119.68 1402.76,-198.43 ; 1402.76,-198.43 1402.76,-198.43 ; 320.08,2045.67 cw(c320.08,2065.35) 320.08,2085.04 1068.11,2085.04 cw(c1068.11,2065.35) 1068.11,2045.67 320.08,2045.67 ; 1250,2045.67 cw(c1250,2065.35) 1250,2085.04 1538.59,2085.04 cw(c1538.59,2065.35) 1538.59,2045.67 1250,2045.67
M2-Board Dimensions:
  text ".Layer_Name" at -580.66,-754.37 h118.11
  text ".GM2" at 1060.87,-754.37 h118.11
M14-Top Assembly:
  text ".Layer_Name" at -580.66,-754.37 h118.11
  text ".GM14" at 1060.87,-754.37 h118.11
M15-Bottom Assembly:
  text ".GM15" at 619.79,-755.63 h118.11
  text ".Layer_Name" at 2246.33,-755.63 h118.11
Drill Drawing:
  drawing of 370 lines, arcs and shapes, not listed
  text "PCB SPECIFICATIONS :" at -985.63,4674.53 h118.11
  text "PCB : TYPE 3" at 4821.13,4667.74 h118.11
  text "A.   MATERIAL :" at -985.63,4517.05 h118.11
  text "FR-4" at 530.12,4517.05 h118.11
  text "TG-170" at 1179.72,4517.05 h118.11
  text "X  TG-150" at 1898.23,4517.05 h118.11
  text "TG-140" at 2528.15,4517.05 h118.11
  text "ASPECT-RATIO, AXE Z :" at 4821.13,4451.21 h118.11
  text "B.   MATERIAL FAMILY :" at -985.63,4398.94 h118.11
  text "N/A" at 530.12,4398.94 h118.11
  text "C.   SOLDERMASK COLOR :" at -985.63,4280.83 h118.11
  text "GREEN" at 530.12,4280.83 h118.11
  text "BLUE" at 1898.23,4280.83 h118.11
  text "BLACK" at 2528.15,4280.83 h118.11
  text "X  WHITE" at 1185,4280 h118.11
  text "6:1 to 8:1 / LEVEL \"B\"" at 4821.86,4185.56 h118.11
  text "D.   SILKSCREEN COLOR :" at -985.63,4162.72 h118.11
  text "WHITE" at 530.12,4162.72 h118.11
  text "YELLOW" at 1179.72,4162.72 h118.11
  text "BLACK" at 1898.23,4162.72 h118.11
  text "X  Blue ink PANTONE 2955" at 2528.15,4162.72 h118.11
  text "E.   SURFACE FINISH :" at -985.63,4044.61 h118.11
  text "X  ENIG" at 530.12,4044.61 h118.11
  text "IMMERSION SILVER" at 1179.72,4044.61 h118.11
  text "IMMERSION TIN" at 2528.15,4044.61 h118.11
  text "MINIMUM PARAMETERS" at 4822.93,3965.05 h118.11
  text "HASL" at 530.12,3926.5 h118.11
  text "HASL (PB-FREE)" at 1179.72,3926.5 h118.11
  text "GOLDEN FINGER" at 2528.15,3926.5 h118.11
  text "F.   IMPEDANCE CONTROL :" at -985.63,3808.39 h118.11
  text "X  NO" at 530.12,3808.39 h118.11
  text "YES  (SEE IMPEDANCE TABLE FOR DETAIL INFORMATION)" at 1179.72,3808.39 h118.11
  text "DEFAULT" at 4822.93,3748.51 h118.11
  text "G.   THROUGH VIA :" at -985.63,3690.28 h118.11
  text "PLUG THE VIAS WHICH ARE COVERED WITH SOLDERMASK ONE OR TWO SIDE." at 530.12,3690.28 h118.11
  text "PLUG MATERIAL :" at 530.12,3572.17 h118.11
  text "X  SOLDERMASK" at 1534.06,3572.17 h118.11
  text "NON-CONDUCTIVE EPOXY." at 2528.15,3572.17 h118.11
  text "TRACKS : 0.127mm           / GAPS : 0.127mm" at 4822.93,3522.13 h118.11
  text "H.   STACK-UP :" at -985.63,3454.06 h118.11
  text "SEE LAYER STACK-UP SEQUENCE FOR OVERALL THICKNESS." at 530.12,3454.06 h118.11
  text "Symbol" at 3632.5,2793.94 h72
  text "Count" at 4138.38,2793.94 h72
  text "Hole Size" at 4738.22,2793.94 h72
  text "Plated" at 5887.88,2793.94 h72
  text "Hole Type" at 6393.76,2793.94 h72
  text "Drill Layer Pair" at 7127.56,2793.94 h72
  text "Via/Pad" at 8627.11,2793.94 h72
  text "Pad Shape" at 9216.96,2793.94 h72
  text "Template" at 9962.76,2793.94 h72
  text "398" at 4138.38,2643.94 h60
  text "0.203mm (8.00mil)" at 4738.22,2643.94 h60
  text "PTH" at 5887.88,2643.94 h60
  text "Round" at 6393.76,2643.94 h60
  text "Top Layer - Bottom Layer" at 7127.56,2643.94 h60
  text "Via" at 8627.11,2643.94 h60
  text "Rounded" at 9216.96,2643.94 h60
  text "(Mixed)" at 9962.76,2643.94 h60
  text "19" at 4138.38,2493.94 h60
  text "0.305mm (12.00mil)" at 4738.22,2493.94 h60
  text "PTH" at 5887.88,2493.94 h60
  text "Round" at 6393.76,2493.94 h60
  text "Top Layer - Bottom Layer" at 7127.56,2493.94 h60
  text "Via" at 8627.11,2493.94 h60
  text "Rounded" at 9216.96,2493.94 h60
  text "v64h30m0mx0" at 9962.76,2493.94 h60
  text "2" at 4138.38,2343.94 h60
  text "0.600mm (23.62mil)" at 4738.22,2343.94 h60
  text "PTH" at 5887.88,2343.94 h60
  text "Slot" at 6393.76,2343.94 h60
  text "Top Layer - Bottom Layer" at 7127.56,2343.94 h60
  text "Pad" at 8627.11,2343.94 h60
  text "Rounded" at 9216.96,2343.94 h60
  text "r190_120h60_130r100m195_125" at 9962.76,2343.94 h60
  text "2" at 4138.38,2193.94 h60
  text "0.900mm (35.43mil)" at 4738.22,2193.94 h60
  text "PTH" at 5887.88,2193.94 h60
  text "Round" at 6393.76,2193.94 h60
  text "Top Layer - Bottom Layer" at 7127.56,2193.94 h60
  text "Pad" at 8627.11,2193.94 h60
  text "Rounded" at 9216.96,2193.94 h60
  text "c150h90m155" at 9962.76,2193.94 h60
  text "104" at 4138.38,2043.94 h60
  text "1.000mm (39.37mil)" at 4738.22,2043.94 h60
  text "PTH" at 5887.88,2043.94 h60
  text "Round" at 6393.76,2043.94 h60
  text "Top Layer - Bottom Layer" at 7127.56,2043.94 h60
  text "Pad" at 8627.11,2043.94 h60
  text "(Mixed)" at 9216.96,2043.94 h60
  text "(Mixed)" at 9962.76,2043.94 h60
  text "32" at 4138.38,1893.94 h60
  text "1.100mm (43.31mil)" at 4738.22,1893.94 h60
  text "PTH" at 5887.88,1893.94 h60
  text "Round" at 6393.76,1893.94 h60
  text "Top Layer - Bottom Layer" at 7127.56,1893.94 h60
  text "Pad" at 8627.11,1893.94 h60
  text "Rounded" at 9216.96,1893.94 h60
  text "(Mixed)" at 9962.76,1893.94 h60
  text "3" at 4138.38,1743.94 h60
  text "3.200mm (125.98mil)" at 4738.22,1743.94 h60
  text "NPTH" at 5887.88,1743.94 h60
  text "Round" at 6393.76,1743.94 h60
  text "Top Layer - Bottom Layer" at 7127.56,1743.94 h60
  text "Pad" at 8627.11,1743.94 h60
  text "Rounded" at 9216.96,1743.94 h60
  text "c320hn320" at 9962.76,1743.94 h60
  text "560 Total" at 4138.38,1593.94 h60
  text "Slot definitions :" at 3632.5,1448.97 h60
  text "Routed Path Length" at 4665.19,1448.97 h60
  text "= Calculated from tool start centre position to tool end centre position." at 5767.86,1448.97 h60
  text "Hole Length" at 4665.19,1348.99 h60
  text "= Routed Path Length + Tool Size = Slot length as defined in the PCB layout" at 5357.99,1348.99 h60
  text "Layer" at 3595.34,745 h60
  text "Name" at 4005.26,745 h60
  text "Material" at 4935,745 h60
  text "Thickness" at 5794.77,745 h60
  text "Constant" at 6444.6,745 h60
  text "Board Layer Stack" at 7014.46,745 h60
  text "Top Overlay" at 4005.26,625 h60
  text "Top Solder" at 4005.26,505 h60
  text "Solder Resist" at 4935,505 h60
  text "0.015mm" at 5794.77,505 h60
  text "3.5" at 6444.6,505 h60
  text "1" at 3595.34,385 h60
  text "Top Layer" at 4005.26,385 h60
  text "Copper" at 4935,385 h60
  text "0.035mm" at 5794.77,385 h60
  text "Dielectric 1" at 4005.26,265 h60
  text "FR-4" at 4935,265 h60
  text "1.473mm" at 5794.77,265 h60
  text "4.2" at 6444.6,265 h60
  text "2" at 3595.34,145 h60
  text "Bottom Layer" at 4005.26,145 h60
  text "Copper" at 4935,145 h60
  text "0.035mm" at 5794.77,145 h60
  text "Bottom Solder" at 4005.26,25 h60
  text "Solder Resist" at 4935,25 h60
  text "0.015mm" at 5794.77,25 h60
  text "3.5" at 6444.6,25 h60
  text "Bottom Overlay" at 4005.26,-95 h60
  text ".Layer_Name" at -580.66,-754.37 h118.11
  text ".DRL" at 1060.87,-754.37 h118.11
M20-Top Title Box:
  circle w10: c2490.37,-1018.96 r51.18
  region: 1920.37,-1062 1496.9,-1062 1536.01,-963.86 1845.37,-963.86 1863.04,-933.96 1949.99,-1034.29
  region: 2471.68,-734.07 1860.37,-734.07 1833.04,-803.96 1785.37,-852.19 1730.37,-778.96 1730.37,-713.96 1775.37,-658.96 1831.9,-644.07 2471.68,-644.07
  lines w10: 1536.01,-963.86 1882.15,-963.86 1761.43,-824.57 cw(c1832.45,-748.04) 1841.9,-644.07 2501.9,-644.07 2471.9,-734.07 ; 1666.47,-634.34 cw(c1761.99,-672.54) 1771.3,-570.09 ; 1668.01,-633.06 1496.9,-1062 2257.64,-1062 ccw(c2267.42,-954.35) 2367.79,-994.49 ; 1736.51,-787.97 1949.99,-1034.29 ; 1746.51,-787.97 1955.37,-1028.96 ; 1746.51,-777.97 1955.37,-1018.96 ; 1750.37,-734.07 2261.9,-734.07 ; 1751.51,-772.97 1960.37,-1013.96 ; 1756.51,-767.97 1965.37,-1008.96 ; 1761.51,-762.97 1970.37,-1003.96 ; 1766.51,-757.97 1975.37,-998.96 ; 1768.67,-681.1 1977.52,-922.09 ; 1771.35,-570.1 2537.09,-570.1 2367.83,-994.4 ; 1771.51,-752.97 1978.22,-991.49 ; 1771.51,-742.97 1980.37,-983.96 ; 1771.51,-732.97 1980.37,-973.96 ; 1771.51,-697.97 1980.37,-938.96 ; 1776.51,-727.97 1985.37,-968.96 ; 1776.51,-712.97 1985.37,-953.96 ; 1830.52,-964.39 ccw(c1834.65,-943.31) 1846.37,-925.32 ; 1873.29,-733.54 ccw(c1872.27,-755.88) 1859.27,-774.07 1952.37,-881.5 cw(c1881.35,-958.03) 1910.2,-1058.37 ; 2120.58,-1053.96 2234.34,-724.07 ; 2129.34,-1052 2242.3,-724.41 ; 2134.34,-1052 2247.3,-724.41 ; 2144.34,-1052 2257.3,-724.41 ; 2154.34,-1052 2267.3,-724.41 ; 2164.34,-1052 2277.3,-724.41 ; 2174.34,-1052 2287.3,-724.41 ; 2184.34,-1052 2297.3,-724.41 ; 2194.34,-1052 2307.3,-724.41 ; 2204.34,-1052 2317.3,-724.41 ; 2212.55,-1053.96 2326.31,-724.07 ; 2326.31,-734.07 2471.68,-734.07 ; 2445.37,-733.96 2475.37,-643.96 ; 2451.9,-734.07 2481.9,-644.07 ; 2461.9,-734.07 2491.9,-644.07
  lines w11.81: -935,-1215 2608.31,-1215 2608.31,-427.6 -935,-427.6 ; -935,-1018.15 1427.2,-1018.15 ; -935,-821.3 1427.2,-821.3 ; -935,-624.45 1427.2,-624.45 ; -934.98,-1215 -934.98,-427.6 ; 639.8,-1215 639.8,-624.45 ; 1427.2,-1215 1427.2,-427.6 ; 2120.58,-1053.96 2212.55,-1053.96
  text "Project: '.Board_Name'" at -895.62,-554.21 h118.11
  text "Layer:" at -895.61,-754.37 h118.11
  text "Gerber:" at 678.74,-754.37 h118.11
  text "Variant: '.VariantName'" at -895.62,-951.22 h118.11
  text "Ref: '.Board_Reference'" at 683.74,-951.22 h118.11
  text "R" at 2470.37,-1048.96 h60
  text "Date: '.Board_Document_Date'" at -895.62,-1148.07 h118.11
  text "Rev: '.Board_PCB_Revision'" at 681.5,-1148.07 h118.11
M21-Bottom Title Box:
  circle w10: c-809.69,-1018.96 r51.18
  region: -791,-734.07 -179.69,-734.07 -152.36,-803.96 -104.69,-852.19 -49.69,-778.96 -49.69,-713.96 -94.69,-658.96 -151.22,-644.07 -791,-644.07
  region: -239.69,-1062 183.78,-1062 144.67,-963.86 -164.69,-963.86 -182.36,-933.96 -269.31,-1034.29
  lines w10: -811.23,-644.07 -781.23,-734.07 ; -801.23,-644.07 -771.23,-734.07 ; -794.69,-643.96 -764.69,-733.96 ; -791.23,-734.07 -821.23,-644.07 -161.22,-644.07 cw(c-151.77,-748.04) -80.76,-824.57 -201.47,-963.86 144.67,-963.86 ; -791,-734.07 -645.63,-734.07 ; -687.15,-994.4 -856.41,-570.1 -90.68,-570.1 ; -687.11,-994.49 ccw(c-586.75,-954.35) -576.96,-1062 183.78,-1062 12.66,-633.06 ; -645.63,-724.07 -531.87,-1053.96 ; -636.62,-724.41 -523.66,-1052 ; -626.62,-724.41 -513.66,-1052 ; -616.62,-724.41 -503.66,-1052 ; -606.62,-724.41 -493.66,-1052 ; -596.62,-724.41 -483.66,-1052 ; -586.62,-724.41 -473.66,-1052 ; -581.23,-734.07 -69.69,-734.07 ; -576.62,-724.41 -463.66,-1052 ; -566.62,-724.41 -453.66,-1052 ; -561.62,-724.41 -448.66,-1052 ; -553.66,-724.07 -439.91,-1053.96 ; -304.69,-968.96 -95.83,-727.97 ; -304.69,-953.96 -95.83,-712.97 ; -299.69,-983.96 -90.83,-742.97 ; -299.69,-973.96 -90.83,-732.97 ; -299.69,-938.96 -90.83,-697.97 ; -297.55,-991.49 -90.83,-752.97 ; -296.85,-922.09 -87.99,-681.1 ; -294.69,-998.96 -85.83,-757.97 ; -289.69,-1003.96 -80.83,-762.97 ; -284.69,-1008.96 -75.83,-767.97 ; -279.69,-1013.96 -70.83,-772.97 ; -274.69,-1028.96 -65.83,-787.97 ; -274.69,-1018.96 -65.83,-777.97 ; -269.31,-1034.29 -55.83,-787.97 ; -229.52,-1058.37 cw(c-200.68,-958.03) -271.69,-881.5 -178.59,-774.07 ccw(c-191.59,-755.88) -192.61,-733.54 ; -165.69,-925.32 ccw(c-153.97,-943.31) -149.84,-964.39 ; -90.63,-570.09 cw(c-81.31,-672.54) 14.2,-634.34
  lines w11.81: -531.87,-1053.96 -439.91,-1053.96 ; 246.1,-1215 246.1,-427.6 ; 246.1,-1018.15 2608.31,-1018.15 ; 246.1,-821.3 2608.31,-821.3 ; 246.1,-624.45 2608.31,-624.45 ; 1033.5,-1215 1033.5,-624.45 ; -935,-1215 -935,-427.6 2608.31,-427.6 2608.31,-1215 -935,-1215
  text "Project: '.Board_Name'" at 2561.3,-554.21 h118.11
  text "Gerber:" at 986.94,-754.37 h118.11
  text "Layer:" at 2561.29,-754.37 h118.11
  text "Ref: '.Board_Reference'" at 986.94,-951.22 h118.11
  text "Variant: '.VariantName'" at 2561.3,-951.22 h118.11
  text "R" at -789.69,-1048.96 h60
  text "Rev: '.Board_PCB_Revision'" at 989.18,-1148.07 h118.11
  text "Date: '.Board_Document_Date'" at 2561.3,-1148.07 h118.11

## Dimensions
0,0 to 19.69,-119.69 on M2-Board Dimensions
1900,860 to 1920.67,686.61 on M2-Board Dimensions
0,700 to 0,500 on M2-Board Dimensions
0,0 to -427.95,-40.95 on M2-Board Dimensions
-300,0 to -427.95,-40.95 on M2-Board Dimensions
-300,0 to 2100,0 on M2-Board Dimensions
-427.95,2970.8 to 2327.96,2970.81 on M2-Board Dimensions
-349.21,3049.55 to 103.55,-198.49 on M2-Board Dimensions
-0.17,5.27 to 1899.83,5.27 on M2-Board Dimensions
